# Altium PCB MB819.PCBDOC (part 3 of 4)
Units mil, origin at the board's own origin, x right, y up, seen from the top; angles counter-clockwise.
Board outline 4505 x 6805 mil, 4 copper layers (TopLayer, MidLayer1, GND, BottomLayer), stack 69.6 mil thick; 336 components, 282 nets, 1318 pads, 584 vias.
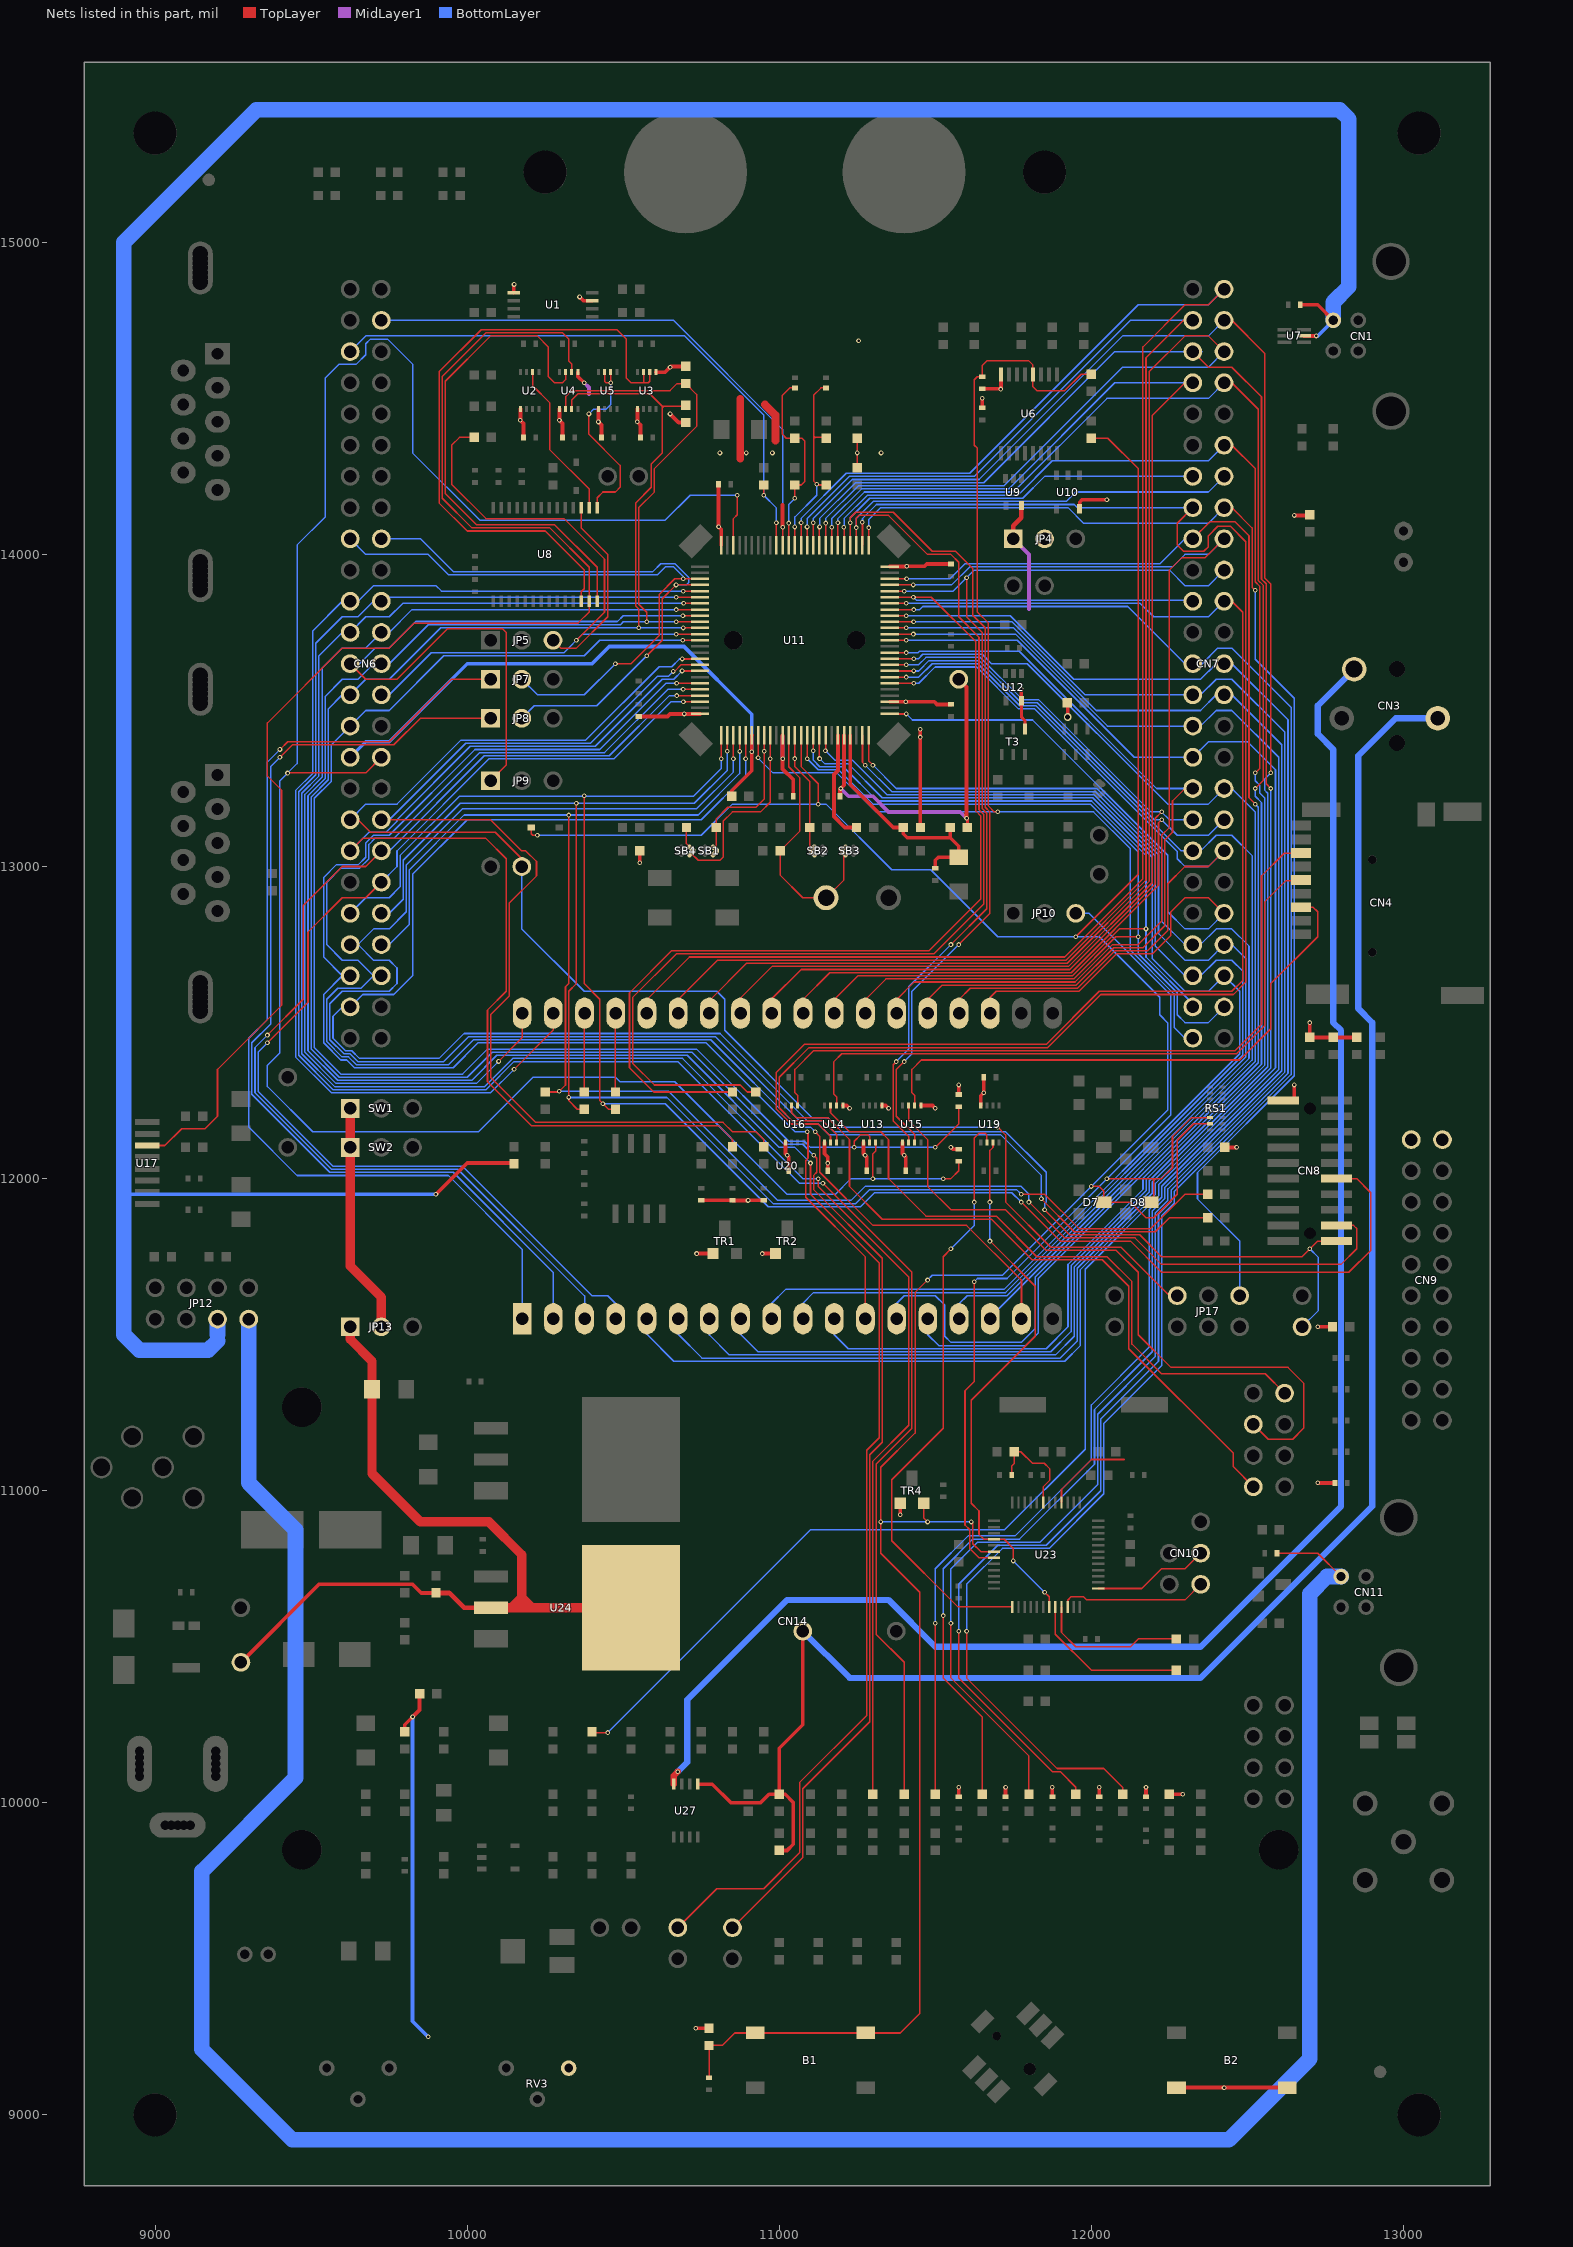
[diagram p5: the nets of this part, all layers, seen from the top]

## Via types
v1: diameter 15, hole 8, TopLayer to BottomLayer, tented both sides, 315 vias
v2: diameter 15, hole 8, TopLayer to BottomLayer, 230 vias
v3: diameter 25, hole 15, TopLayer to BottomLayer, tented both sides, 31 vias
v4: diameter 25, hole 16, TopLayer to BottomLayer, 6 vias
v5: diameter 25, hole 16, TopLayer to BottomLayer, tented both sides, 2 vias

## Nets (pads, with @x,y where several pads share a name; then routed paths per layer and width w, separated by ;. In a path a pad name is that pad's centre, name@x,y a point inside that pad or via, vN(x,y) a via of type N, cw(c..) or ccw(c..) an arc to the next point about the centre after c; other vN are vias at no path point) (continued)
PB5: CN6.35 JP11.1 JP17.2 U11.91 | length 4895.4
  TopLayer w5: CN6.35@9625,13150 9650,13150 9690,13110 10090,13110 10175,13025 JP11.1@10175,13000 ; v2(10689.06,13665) U11.91@10734.06,13665 ; v2(11700,12165) 11725,12140 11725,11925 11870,11780 12095,11780 JP17.2@12250,11625
  BottomLayer w5: CN6.35@9625,13150 9675,13200 9775,13200 9980,13405 10380,13405 10615,13640 10655.15,13640 10680.15,13665 v2(10689.06,13665) ; JP11.1@10175,13000 10175,12800 10375,12600 10800,12600 10825,12575 10825,12475 11105,12195 11155,12195 11185,12165 v2(11700,12165)
PB6: CN6.36 R69.1 U11.92 | length 3511.2
  TopLayer w5: CN6.36@9725,13150 10075,13150 10175,13050 10188,13050 10222,13016 10222,12970 10135,12883 10135,12585 10075,12525 10075,12325 10220,12180 10820,12180 10850,12150 10925,12150 10950,12125 R69.1@10950,12102.5 ; v2(10660,13625) 10664.06,13625 10685.31,13646.26 U11.92@10745.87,13646.26
  BottomLayer w5: CN6.36@9725,13150 9750,13150 9995,13395 10395,13395 10610,13610 10645,13610 v2(10660,13625)
PB7: CN6.37 R62.1 U11.93 | length 3530.1
  TopLayer w5: CN6.37@9625,13050 9665,13090 10060,13090 10125,13025 10125,12600 10065,12540 10065,12310 10205,12170 10805,12170 10850,12125 R62.1@10850,12102.5 ; v2(10688.43,13626.57) U11.93@10745.87,13626.57
  BottomLayer w5: CN6.37@9625,13050 9685,13110 9740,13110 9775,13145 9775,13150 10010,13385 10410,13385 10625,13600 10661.85,13600 v2(10688.43,13626.57)
PB9: CN6.46 U11.96 U20.17 | length 5011.4
  TopLayer w5: v1(10691.48,13567.52) U11.96@10745.87,13567.52 ; v2(11115,12150) 11130,12135 11130,12020 11300,11850 11600,11850 11776,11674 U20.17@11776,11551
  BottomLayer w5: CN6.46@9725,12650 CN6.46@9700,12650 ; v1(10691.48,13567.52) 10642.52,13567.52 10440,13365 10040,13365 9765,13090 9704.14,13090 9685,13070.86 9685,13025 9655,12995 9595,12995 9550,12950 9550,12750 9600,12700 9650,12700 CN6.46@9700,12650 ; v2(11115,12150) 11100,12165 11060,12165 10780,12445 10020,12445 9940,12365 9645,12365 9620,12390 9599.14,12390 9550,12439.14 9550,12575 9585,12610 9660,12610 CN6.46@9700,12650
PB12: CN7.16 JP17.6 U11.51 | length 4095.5
  TopLayer w5: U11.51@11286.22,14029.13 v1(11286.22,14086.22) ; CN7.16@12425,14150 12450,14150 12515,14085 12515,13895 v2(12525,13885)
  BottomLayer w5: v1(11286.22,14086.22) 11286.22,14111.22 11325,14150 11925,14150 11975,14100 12375,14100 CN7.16@12425,14150 ; JP17.6@12475,11625 12475,11800 12340,11935 12340,12019.29 12650,12329.29 12650,13538.89 12525,13663.89 v2(12525,13885)
PB13: CN7.15 U11.52 U14.3 | length 4985.6
  TopLayer w5: U14.3@11183.84,12115.94 11183.84,12141.16 11140,12185 11042.13,12185 11000,12227.13 11000,12325 11095,12420 11860,12420 12030,12590 12455,12590 12495,12630 12495,14040.86 12445.86,14090 12405,14090 12375,14060 12375,14025 12360,14010 12295,14010 12275,14030 12275,14100 CN7.15@12325,14150 ; v1(11266,14103) 11266.54,14102.46 U11.52@11266.54,14029.13
  BottomLayer w5: v1@11266.54,14102.46 11266.54,14115 11311.54,14160 11945,14160 11955,14150 CN7.15@12325,14150
PB14: CN7.14 R58.1 U11.53 | length 4765
  TopLayer w5: R58.1@10925,12277.5 10897.5,12277.5 10875,12300 10600,12300 10530,12370 10530,12580 10670,12720 11495,12720 11655,12880 11655,13166.72 11640,13181.72 11640,13735 11575,13800 11575,13975 11550,14000 11475,14000 11350,14125 11255,14125 11246.85,14116.85 U11.53@11246.85,14029.13
  BottomLayer w5: v1(11246.85,14086.15) 11246.85,14115 11301.85,14170 11920,14170 11950,14200 12375,14200 CN7.14@12425,14250
PB15: CN7.13 U11.54 U15.3 | length 3741.5
  TopLayer w5: U11.54@11227.17,14029.13 11227.17,14117.17 11245,14135 11365,14135 11490,14010 11565,14010 11620,13955 11620,13805 11660,13765 11660,13190 11675,13175 11675,12850 v2(11575,12750) ; v2(11400,12375) 11375,12350 11375,12200 11433.84,12141.16 U15.3@11433.84,12115.94
  BottomLayer w5: v2(11227.17,14101.83) 11227.17,14117.17 11290,14180 11780,14180 11850,14250 CN7.13@12325,14250 ; v2(11400,12375) 11425,12400 11425,12600 v2(11575,12750)
PC6: R14.1 R23.1 R30.1 U11.63 | length 646.4
  TopLayer w5: U11.63@11050,14029.13 v1(11050,14088) ; 11110,14370 11115,14375 11110,14380 ; 11110,14375 R23.1@11147.5,14375 ; R30.1@11150,14222.5 11122.5,14222.5 11110,14235 11110,14510 11133.5,14533.5 R14.1@11150,14533.5
  BottomLayer w5: v1(11050,14088) 11050,14120 11120,14190 v1(11120,14225)
PC7: R13.1 R22.1 R28.2 U11.64 | length 622.1
  TopLayer w5: U11.64@11030.31,14029.13 v1(11030.31,14100.69) ; v1(11050,14180) R28.2@11050,14222.5 11070.5,14222.5 11081,14233 11081,14364 11072.5,14372.5 11022.5,14372.5 11010,14385 11010,14510 11033.5,14533.5 R13.1@11050,14533.5
  BottomLayer w5: v1@11030,14101 11030,14160 v1(11050,14180)
PC8: C18.1 CN6.4 R24.1 U11.65 | length 2289.3
  TopLayer w5: 11009.97,14159.1 11010.63,14158.44 ; U11.65@11010.63,14029.13 v1(11010.63,14087.37) ; C18.1@11250,14277.5 R24.1@11250,14372.5
  TopLayer w12: v1(11010.63,14087.37) 11010.63,14158.44
  TopLayer w25: 10875,14307 10875,14499 ; 10954,14480 10987.5,14446.5 10987.5,14365.16
  BottomLayer w5: CN6.4@9725,14750 10660.86,14750 11010.63,14400.23 v1(11010.63,14087.37)
  other v1: 10810,14325 10894,14325 10978,14325 11250,14325 11326,14325 11254,14685
PC9: CN6.5 R29.1 U11.66 | length 1917.7
  TopLayer w5: v1(10950,14190) R29.1@10950,14222.5 ; U11.66@10990.94,14029.13 v1(10990.94,14101.94)
  BottomLayer w5: CN6.5@9625,14650 9675,14700 10696.72,14700 10950,14446.72 v1(10950,14190) 10990.94,14149.06 v1(10990.94,14101.94)
PC10: CN6.17 JP7.2 U11.78 | length 1968.3
  TopLayer w5: v2(10475,13650) 10525,13650 10615,13740 10615,13871.85 10665,13921.85 U11.78@10745.87,13921.85
  BottomLayer w5: CN6.17@9625,14050 9675,14000 9875,14000 9940,13935 10610,13935 10635,13960 10661.86,13960 10691.85,13930.01 v1(10691.85,13921.85) ; JP7.2@10175,13600 10225,13550 10375,13550 v2(10475,13650)
PC11: CN6.18 JP8.2 U11.79 | length 1942.9
  TopLayer w5: v2(10575,13675) 10625,13725 10625,13858 v1(10669.17,13902.17) U11.79@10745.87,13902.17
  BottomLayer w5: CN6.18@9725,14050 9850,14050 9955,13945 10595,13945 10620,13970 10666,13970 10710,13926 10710,13910 10702.17,13902.17 v1(10669.17,13902.17) ; JP8.2@10175,13475 10215,13515 10415,13515 v2(10575,13675)
PC13: CN7.49 R26.2 R31.1 U6.12 U11.7 | length 4036.1
  TopLayer w5: v2(10931.89,13348.11) U11.7@10931.89,13420.87 ; v2(11700,13175) 11689.14,13175 11670,13194.14 11670,13780 11635,13815 11635,14340 11625,14350 11625,14560 11634.5,14569.5 R26.2@11650,14569.5 11650,14605 11665,14620 11800,14620 11812.8,14607.2 11812.8,14537.2 11825,14525 11915,14525 11967.5,14577.5 R31.1@12000,14577.5
  BottomLayer w5: v2(10931.89,13348.11) 10980,13300 11185,13300 11310,13175 12007.01,13175 12125,13057.01 12125,12731.72 12265,12591.72 12265,12485 12300,12450 CN7.49@12325,12450
PC14: R37.2 SB1.1 U11.8 | length 489
  TopLayer w5: SB1.1@10800,13050 10797.5,13052.5 10797.5,13152.5 10835,13190 10925,13190 10951.57,13216.57 U11.8@10951.57,13420.87 ; v1@10951.57,13369.43 v1(10952,13369)
PC15: R38.2 SB4.1 U11.9 | length 694.9
  TopLayer w5: R38.2@10702.5,13125 10702.5,13073.5 SB4.1@10718,13058 ; SB4.1@10718,13042 10740,13020 10810,13020 10820,13030 10820,13145 10850,13175 10940,13175 10971.26,13206.26 U11.9@10971.26,13420.87
  other v1: 10971.26,13345.74
PD0: CN6.22 R111.1 U11.81 | length 6714.7
  TopLayer w5: v1(10669.8,13862.8) U11.81@10745.87,13862.8 ; v2(11140,11985) 11425,11700 11425,11200 11310,11085 11310,10540 11400,10450 R111.1@11400,10027.5
  MidLayer1 w5: CN6.22@9705,13850 CN6.22@9725,13850
  BottomLayer w5: CN6.22@9700,13850 9650,13800 9600,13800 9515,13715 9515,13294.29 9460,13239.29 9460,12395 9570,12285 10060,12285 10150,12375 10675,12375 11065,11985 v2(11140,11985) ; CN6.22@9725,13850 9737.8,13862.8 v1(10669.8,13862.8)
PD1: CN6.23 R125.1 U11.82 | length 6648.8
  TopLayer w5: v1(10693.11,13843.11) U11.82@10745.87,13843.11 ; v2(11125,12000) 11125,11975 11415,11685 11415,11210 11300,11095 R125.1@11300,10027.5
  MidLayer1 w5: CN6.23@9600,13750 CN6.23@9625,13750
  BottomLayer w5: v1(10693.11,13843.11) 9793.11,13843.11 9750,13800 9675,13800 CN6.23@9625,13750 9600,13750 9525,13675 9525,13290.15 9470,13235.15 9470,12400 9575,12295 10055.86,12295 10145.86,12385 10690,12385 11075,12000 v2(11125,12000)
PD3: CN6.25 JP9.1 U11.84 | length 2273.5
  TopLayer w5: CN6.25@9625,13650 9675,13600 9775,13600 9937.5,13762.5 10112.5,13762.5 10125,13750 10125,13325 JP9.1@10075,13275 ; v1(10691.26,13803.74) U11.84@10745.87,13803.74
  BottomLayer w5: CN6.25@9625,13650 9655,13650 9705,13700 9750,13700 9835,13785 10481.26,13785 10500,13803.74 v1(10691.26,13803.74)
PD4: CN6.26 JP18.2 R12.1 U4.2 U11.85 | length 8485.7
  TopLayer w5: U4.2@10315.16,14465.94 10315.16,14505.16 10335,14525 10650,14525 10672.5,14547.5 R12.1@10700,14547.5 10735,14512.5 10735,14410 10600,14275 10600,14200 10550,14150 10550,13840 10575,13815 v2(10575,13784.06) ; v1(10669.94,13784.06) U11.85@10745.87,13784.06 ; JP18.2@10675,9600 10800,9725 10950,9725 11065,9840 11065,10065 11280,10280 11280,11130 11320,11170 11320,11730 11100,11950 v2(11100,12050)
  BottomLayer w5: v1(10669.94,13784.06) 10500,13784.06 10490.94,13775 9875,13775 9750,13650 9700,13650 9650,13600 9600,13600 9545,13545 9545,13281.86 9490,13226.86 9490,12410 9585,12315 10015,12315 10095,12395 10705,12395 11000,12100 11050,12100 v2(11100,12050)
PD5: CN6.27 JP19.2 R21.1 U4.3 U11.86 | length 8173.9
  TopLayer w5: U4.3@10334.84,14465.94 10334.84,14494.84 10355,14515 10585,14515 10625,14475 ; v2(10550,13765) 10550,13825 10540,13835 10540,14165 10590,14215 10590,14290 10625,14325 10625,14475 ; 10625,14470 10630,14475 ; v1(10692.63,13764.37) U11.86@10745.87,13764.37 ; R21.1@10697.5,14475 10625,14475 ; JP19.2@10850,9600 11075,9825 11075,10045 11290,10260 11290,11115 11330,11155 11330,11745 11110,11965 11110,12010 11120,12020 11120,12065 v2(11110,12075)
  BottomLayer w5: v1@10692,13765 9915,13765 9750,13600 9675,13600 CN6.27@9625,13550 9600,13550 9555,13505 9555,13277.72 9500,13222.72 9500,12415 9590,12325 10000,12325 10080,12405 10720,12405 11015,12110 11075,12110 v2(11110,12075)
PD6: CN6.28 R19.1 U11.87 | length 2196.1
  TopLayer w5: R19.1@10022.5,14375 9975,14375 9950,14350 9950,14225 10060,14115 10310,14115 10440,13985 10440,13815 v2(10350,13725) ; v1(10670.31,13744.69) U11.87@10745.87,13744.69
  BottomLayer w5: CN6.28@9725,13550 9750,13550 9885,13685 10310,13685 10369.69,13744.69 v1(10670.31,13744.69)
PD7: CN6.29 R59.2 U11.88 U13.2 | length 4761.9
  TopLayer w5: v1(10691,13725) U11.88@10745.87,13725 ; v2(11240,12100) 11240,12120 11260,12140 11285,12140 11289.16,12135.84 U13.2@11289.16,12115.94 ; v2(11500,12100) 11575,12175 R59.2@11575,12230.5
  BottomLayer w5: v1(10691,13725) 10425,13725 10375,13675 9925,13675 9750,13500 9675,13500 9565,13390 9565,13273.58 9510,13218.58 9510,12420 9595,12335 9985,12335 10065,12415 10735,12415 11030,12120 11080,12120 11100,12100 v2(11500,12100)
PE2: CN6.41 CN8.12 R77.1 U11.1 | length 5680.1
  TopLayer w5: v2(10375,13227) 10375,12625 10425,12575 10425,12250 10452.5,12222.5 R77.1@10475,12222.5 ; v1(10813.78,13345.22) U11.1@10813.78,13420.87 ; v2(11775,11925) 11900,11800 12125,11800 12225,11700 12825,11700 12895,11770 12895,11955 12850,12000 CN8.12@12775,12000
  BottomLayer w5: CN6.41@9625,12850 9675,12900 9750,12900 9785,12935 9785,13035 9975,13225 10373,13225 v2(10375,13227) ; v2@10375,13225 10725,13225 10813.78,13313.78 v1(10813.78,13345.22) ; v2(10435,12240) 10635,12240 10965,11910 11260,11910 11305,11955 11745,11955 v2(11775,11925)
PE3: CN6.42 R70.2 R78.1 U11.2 | length 4812.6
  TopLayer w5: v2(10350,13203) 10350,12625 10325,12600 10325,12250 10352.5,12222.5 R78.1@10375,12222.5 ; v1@10833.46,13369.46 U11.2@10833.46,13420.87 ; v2(11775,11950) 11850,11950 11960,11840 12190,11840 12300,11950 R70.2@12372.5,11950
  BottomLayer w5: CN6.42@9725,12850 9750,12850 9795,12895 9795,13020 9977.5,13202.5 v2@10350,13202.5 ; v2(10325,12260) 10640,12260 10980,11920 11245,11920 11290,11965 11760,11965 v2(11775,11950) ; v2(10350,13203) 10350.5,13202.5 10727.5,13202.5 10833,13308 v1(10833,13369)
PE4: CN6.43 R71.2 U11.3 | length 5421.7
  TopLayer w5: v1@10853.15,13345.15 U11.3@10853.15,13420.87 ; v2(11840,11935) 11945,11830 12205,11830 12250,11875 R71.2@12372.5,11875
  BottomLayer w5: CN6.43@9625,12750 CN6.43@9650,12750 ; v1(10853,13345) 10853,13303 10735,13185 9985,13185 9805,13005 9805,12855 9750,12800 9700,12800 CN6.43@9650,12750 ; v2(11840,11935) 11840,12010 11710,12140 11160,12140 11125,12175 11075,12175 10795,12455 10005,12455 9925,12375 9649.14,12375 9624.14,12400 9605,12400 9560,12445 9560,12560 9600,12600 9750,12600 9775,12625 9775,12675 9750,12700 9700,12700 CN6.43@9650,12750
PE5: CN6.44 CN8.18 R88.1 U11.4 | length 5535.4
  TopLayer w5: R88.1@10250,12277.5 10292.5,12277.5 10315,12300 10315,12615 10325,12625 v2(10325,13165) ; v1(10872.83,13368.83) U11.4@10872.83,13420.87 ; v2(11800,11925) 11915,11810 12140,11810 12225,11725 12800,11725 12850,11775 12850,11840 12840,11850 CN8.18@12785,11850
  BottomLayer w5: CN6.44@9725,12750 9750,12750 9815,12815 9815,12990 9990,13165 10740,13165 10872.83,13297.83 v1(10872.83,13368.83) ; v2(10295,12280) 10645,12280 10995,11930 11230,11930 11275,11975 11775,11975 11800,11950 v2(11800,11925)
PE6: CN6.47 CN8.20 JP2.2 U11.5 | length 5982.9
  TopLayer w5: v1@10892.52,13345.52 U11.5@10892.52,13420.87 ; v2(11850,11900) 11930,11820 12155,11820 12225,11750 12675,11750 12725,11800 CN8.20@12785,11800
  BottomLayer w5: v1(10892,13345) 10892,13292 10750,13150 10000,13150 9825,12975 9825,12650 9765,12590 9665,12590 CN6.47@9625,12550 9600,12550 9570,12520 9570,12450 9610,12410 9630,12410 9655,12385 9910,12385 9990,12465 10810,12465 11090,12185 11140,12185 11175,12150 11725,12150 11855,12020 11855,11925 11850,11920 v2(11850,11900) ; JP2.2@12675,11525 12727.5,11577.5 12727.5,11747.5 v2(12700,11775)
PE7: CN7.31 R75.1 U11.38 | length 5837.5
  TopLayer w5: R75.1@10402.5,10225 v2(10450,10225) ; U11.38@11354.13,13725 v1(11407,13725) ; CN7.31@12325,13350 CN7.31@12330,13350
  BottomLayer w5: v2(10450,10225) 11100,10875 11722,10875 11980,11133 11980,11709.29 12215.33,11944.62 12215.33,11980.48 12590,12355.15 12590,13310 12500,13400 12375,13400 CN7.31@12325,13350 12137.26,13350 11762.26,13725 v1(11407,13725)
PE8: CN7.29 R112.2 U11.39 | length 5316.8
  TopLayer w5: U11.39@11354.13,13744.69 v1@11429.69,13744.69 ; R112.2@11500,10027.5 v2(11500,10575)
  BottomLayer w5: v1@11429.69,13744.69 11756.72,13744.69 12051.4,13450 12350,13450 12400,13500 12450,13500 12600,13350 12600,12350 12225.33,11975.33 12225.33,11940.48 12185,11900.15 12185,11460 12000,11275 12000,11100 11755,10855 11605,10855 11500,10750 v2(11500,10575)
  other v1: 11430,13745
PE9: CN7.28 R126.2 U11.40 | length 5378.9
  TopLayer w5: U11.40@11354.13,13764.37 v1@11406.37,13764.37 ; v2(11525,10600) 11525,10400 11650,10275 R126.2@11650,10027.5
  BottomLayer w5: v1@11406.37,13764.37 11751.18,13764.37 12015.55,13500 12350,13500 CN7.28@12400,13550 ; v2(11525,10600) 11525,10750 11620,10845 11770.01,10845 12010,11084.99 12010,11260 12195,11445 12195,11896 12235.33,11936.34 12235.33,11971.19 12610,12345.86 12610,13390 12450,13550 CN7.28@12425,13550
  other v1: 11407,13765
PE10: CN7.27 R127.2 U11.41 | length 5520.4
  TopLayer w5: U11.41@11354.13,13784.06 v1(11430.06,13784.06) ; v2(11550,10575) 11550,10400 11800,10150 R127.2@11800,10027.5
  BottomLayer w5: v1(11430.06,13784.06) 11745.63,13784.06 11979.69,13550 12350,13550 12400,13600 12450,13600 12620,13430 12620,12341.72 12245.33,11967.05 12245.33,11930.33 12205,11890 12205,11430 12020,11245 12020,11020 11835,10835 11635,10835 11550,10750 v2(11550,10575)
PE11: CN7.26 R117.2 U11.42 | length 5570.8
  TopLayer w5: U11.42@11354.13,13803.74 v1(11407.26,13803.74) ; v2(11575,10550) 11575,10400 11875,10100 11900,10100 11950,10050 R117.2@11950,10027.5
  BottomLayer w5: v1(11407.26,13803.74) 11740.09,13803.74 11943.83,13600 12350,13600 CN7.26@12400,13650 ; v2(11575,10550) 11575,10700 11700,10825 11855,10825 12030,11000 12030,11230 12215,11415 12215,11885 12255.33,11925.33 12255.33,11962.91 12630,12337.57 12630,13470 12450,13650 CN7.26@12425,13650
PE12: CN7.25 R118.2 U11.43 | length 5761.3
  TopLayer w5: U11.43@11354.13,13823.43 v1(11430.57,13823.43) ; v2(11600,10550) 11600,10400 11890,10110 12040,10110 12100,10050 R118.2@12100,10027.5
  BottomLayer w5: v1(11430.57,13823.43) 11450,13823.43 11459.69,13833.11 12116.89,13833.11 12300,13650 12355,13650 12405,13700 12450,13700 12640,13510 12640,12333.43 12265.33,11958.77 12265.33,11921.19 12225,11880.86 12225,11400 12040,11215 12040,10990 11865,10815 11715,10815 11600,10700 v2(11600,10550)
PE13: CN7.22 U11.44 U14.2 | length 4328.3
  TopLayer w5: U14.2@11164.16,12115.94 11164.16,12135.84 11125,12175 11037.98,12175 10990,12222.98 10990,12340 11080,12430 11855,12430 12025,12600 12450,12600 12485,12635 12485,13815 12450,13850 CN7.22@12425,13850 ; U11.44@11354.13,13843.11 v1(11407.11,13843.11)
  BottomLayer w5: v1(11407.11,13843.11) 12156.89,13843.11 12200,13800 12375,13800 CN7.22@12425,13850
PE14: CN7.21 R57.1 U11.45 | length 3913.5
  TopLayer w5: R57.1@10850,12277.5 10597.5,12277.5 10520,12355 10520,12595 10655,12730 11480,12730 11645,12895 11645,13162.57 11630,13177.57 11630,13720 11487,13863 v1(11430,13863) ; U11.45@11354.13,13862.8 v1@11429.8,13862.8
  BottomLayer w5: v1(11430,13863) 11439.89,13853.11 CN7.21@12321.89,13853.11
PE15: CN7.20 U11.46 U15.2 | length 3120.9
  TopLayer w5: U11.46@11354.13,13882.48 v2(11400,13882.48) ; v2(11375,12375) 11365,12365 11365,12185 11414.16,12135.84 U15.2@11414.16,12115.94 ; v2(11550,12750) 11665,12865 11665,13170.86 11650,13185.86 11650,13750 11600,13800 v2(11600,13925)
  BottomLayer w5: v2(11375,12375) 11415,12415 11415,12615 v2(11550,12750) ; v2(11400,13882.48) 11557.48,13882.48 11625,13950 12250,13950 12300,13900 12375,13900 CN7.20@12425,13950
PH0: C30.1 SB3.1 U11.12 X2.2 | length 834.1
  TopLayer w5: 11030,13370 11030,13320 11065,13285 11065,13112.5 C30.1@11002.5,13050 11002.5,12972.5 11075,12900 X2.2@11150,12900 ; 11030.31,13370.31 U11.12@11030.31,13420.87 ; X2.2@11150,12902.5 X2.2@11150,12900 ; SB3.1@11207,13042 11207,12957 X2.2@11150,12900
PH1: R39.1 SB2.1 U11.13 | length 386.5
  TopLayer w5: U11.13@11050,13420.87 11050,13320 11097.5,13272.5 11097.5,13067.5 SB2.1@11107,13058
  other v1: 11050,13346
PH2: CN6.32 R64.2 U11.73 U13.3 | length 7350.6
  TopLayer w5: v2(9424.4,13299.4) 9425,13300 9675,13300 CN6.32@9725,13350 ; U11.73@10853.15,14029.13 10853.15,14115 10865,14126.85 v2(10865,14190) ; v2(11300,12000) 11300,12080 11308.84,12088.84 U13.3@11308.84,12115.94 ; v2(11525,12000) 11550,12000 11575,12025 R64.2@11575,12055.5
  BottomLayer w5: v2(10865,14190) 10715,14190 10635,14110 10040,14110 9825,14325 9825,14610 9745,14690 9690,14690 9675,14675 9675,14640 9645,14610 9590,14610 9545,14565 9545,14120 9455,14030 9455,13330 9400,13275 9400,12403.28 9360,12363.28 9360,12295 9505,12150 10035.86,12150 10210.86,12325 10475,12325 10490,12310 10665,12310 11025,11950 11180,11950 11230,12000 v2(11525,12000)
RESET#: B1.2 B1.3 C85.2 D2.1 D7.3 R49.2 R137.1 RS1.13 TR4.1 U11.14 U23.18 | length 10176.3
  TopLayer w5: D2.1@10205,13125 10205,13105 10210,13100 v2(10225,13100) ; C85.2@10775,9119.5 R137.1@10775,9222.5 10817.5,9222.5 10857.5,9262.5 11387.5,9262.5 11450,9325 11450,10675 11325,10800 11325,11075 11435,11185 11435,11635 v2(11475,11675) ; U11.14@11069.68,13420.87 11069.68,13320.32 11125,13265 v2(11125,13200) ; TR4.1@11462.5,10960 11462.5,10912.5 v2(11475,10900) ; v2(11615,10900) 11620,10895 11620,10830 11645.16,10804.84 U23.18@11687.68,10804.84 ; v2(11950,12775) 12150,12975 12150,14275 12052.5,14372.5 R49.2@12000,14372.5 ; v2(12000,11975) 12025,11975 12040,11960 D7.3@12040,11924.5 12125.5,11924.5 12175,11875 12200,11875 12275,11950 12275,12123 12327.79,12175.79 RS1.13@12380,12175.79
  BottomLayer w5: v2(10225,13100) 10750,13100 10850,13200 11150,13200 11360,12990 11485,12990 11700,12775 12025,12775 12218.99,12581.01 12218.99,12525 12245,12498.99 12245,12220 11715,11690 11490,11690 v2(11475,11675) ; v2(11325,10900) v2(11615,10900)
SEG0: CN7.44 U11.24 U20.15 | length 3375.3
  TopLayer w5: U11.24@11266.54,13420.87 11266.54,13333.46 v2(11275,13325)
  BottomLayer w5: v2(11275,13325) 11360,13240 12012.72,13240 12215,13037.72 12215,12785 12300,12700 12375,12700 CN7.44@12425,12750 12450,12750 12495,12705 12495,12390 11730,11625 11602,11625 11576,11599 U20.15@11576,11551
SEG1: CN7.43 U11.25 U20.16 | length 3252.7
  TopLayer w5: U11.25@11286.22,13420.87 11286.22,13338.78 v2(11300,13325)
  BottomLayer w5: v2(11300,13325) 11375,13250 12016.86,13250 12225,13041.86 12225,12825 12300,12750 12350,12750 12400,12800 12450,12800 12505,12745 12505,12385 11676,11556 U20.16@11676,11551
SEG2: CN7.42 U11.26 U20.21 | length 2504.7
  TopLayer w5: U11.26@11354.13,13488.78 v1(11407.22,13488.78) ; U20.21@11676,12530 11676,12581 11695,12600 11960,12600 12080,12720 12195,12720 12255,12780 12255,12855 12300,12900 12375,12900 CN7.42@12425,12850
  BottomLayer w5: v1(11407.22,13488.78) 11426.57,13469.43 11811.57,13469.43 12245,13036 12245,12855 12300,12800 12375,12800 CN7.42@12425,12850 CN7.42@12450,12850
SEG3: CN7.38 U11.31 U20.22 | length 2571.1
  TopLayer w5: U11.31@11354.13,13587.2 v1(11430.8,13587.2) ; U20.22@11575,12531 U20.22@11576,12530 11576,12574 11612,12610 11955.86,12610 12075.86,12730 12180,12730 12245,12795 12245,12945 12300,13000 12375,13000 CN7.38@12425,13050
  BottomLayer w5: v1(11430.8,13587.2) 11447.2,13587.2 11499.3,13639.3 11632.42,13639.3 11766.72,13505 11818.43,13505 12275,13048.43 12275,13025 12300,13000 12375,13000 CN7.38@12425,13050
SEG4: CN7.37 U11.32 U20.13 | length 3896.1
  TopLayer w5: U11.32@11354.13,13606.89 11406.89,13606.89 v1(11407,13607)
  BottomLayer w5: U20.13@11376,11551 11376,11601 11400,11625 11500,11625 11530,11595 11530,11495 11550,11475 11775,11475 11820,11520 11820,11685 12515,12380 12515,13035 12450,13100 12400,13100 CN7.37@12350,13050 ; v1@11406.89,13606.89 11446.89,13606.89 11489.9,13649.9 11635.96,13649.9 11770.86,13515 11822.57,13515 12287.57,13050 CN7.37@12325,13050
SEG5: CN7.34 U11.35 U20.14 | length 3821.2
  TopLayer w5: U11.35@11354.13,13665.94 v1(11430.94,13665.94)
  BottomLayer w5: v1(11430.94,13665.94) 11445.94,13665.94 11460,13680 11650,13680 11680,13650 11794.83,13650 12244.83,13200 12375,13200 CN7.34@12425,13250 12450,13250 12525,13175 12525,12375 11830,11680 11830,11505 11790,11465 11511,11465 11476,11500 U20.14@11476,11551
SEG6: CN7.33 U11.36 U20.23 | length 2547.6
  TopLayer w5: U11.36@11354.13,13685.63 v1(11406.63,13685.63) ; U20.23@11476,12530 11476,12574 11522,12620 11951.72,12620 12071.72,12740 12165,12740 12235,12810 12235,13085 12260,13110 12260,13210 12300,13250 CN7.33@12325,13250
  BottomLayer w5: v1(11406.63,13685.63) 11445.63,13685.63 11450,13690 11768.98,13690 12208.98,13250 CN7.33@12325,13250
SEG10: CN7.18 U11.47 U20.24 | length 3480.8
  TopLayer w5: U11.47@11354.13,13902.17 v1(11429.17,13902.17) ; U20.24@11376,12530 11376,12574 11432,12630 11947.57,12630 12067.57,12750 12150,12750 12225,12825 12225,13100 12250,13125 12250,13950 12290,13990 12365,13990 CN7.18@12425,14050
  BottomLayer w5: v1(11429.17,13902.17) 11552.17,13902.17 11610,13960 12260,13960 12300,14000 12375,14000 CN7.18@12425,14050
SEG11: CN7.17 U11.48 U20.11 | length 4893.1
  TopLayer w5: U11.48@11354.13,13921.85 v1(11407.85,13921.85) ; CN7.17@12325,14050 12380,14105 12460,14105 12505,14060 12505,13220 v2(12525,13200)
  BottomLayer w5: U20.11@11176,11551 11176,11500 11221,11455 11855,11455 11925,11525 11925,11725 12165.33,11965.33 12165.33,12001.19 12535,12370.86 12535,13190 v2(12525,13200) ; v1(11407.85,13921.85) 11546.85,13921.85 11595,13970 12220,13970 12300,14050 CN7.17@12325,14050
SEG16: CN6.45 U11.95 U20.12 | length 4486.3
  TopLayer w5: v1(10670.8,13587.2) U11.95@10745.87,13587.2 ; v2(11090,12150) 11092.03,12147.97 11092.03,12065 11084.5,12057.47 11084.5,11940.5 11276,11749 U20.12@11276,11551
  BottomLayer w5: v1(10670.8,13587.2) 10637.2,13587.2 10425,13375 10025,13375 9750,13100 9700,13100 9675,13075 9675,13030 9650,13005 9580,13005 9540,12965 9540,12710 9600,12650 9540,12590 9540,12435 9595,12380 9614.14,12380 9639.14,12355 9955,12355 10035,12435 10765,12435 11050,12150 v2(11090,12150)
SEG18: CN7.48 U11.15 U20.25 | length 3015.2
  TopLayer w5: v1(11089.37,13345.63) U11.15@11089.37,13420.87 ; U20.25@11276,12530 11276,12574 11342,12640 11943.43,12640 12078.43,12775 v2(12150,12775)
  BottomLayer w5: v1(11089.37,13345.63) 11125,13310 11190,13310 11300,13200 11996.15,13200 12150,13046.15 12150,12720.86 12275,12595.86 12275,12525 12300,12500 12375,12500 CN7.48@12425,12550
SEG19: CN7.47 U11.16 U20.26 | length 2956.5
  TopLayer w5: v1@11109.06,13371.06 U11.16@11109.06,13420.87 ; U20.26@11176,12530 11176,12574 11252,12650 11939.29,12650 12089.29,12800 v2(12175,12800)
  BottomLayer w5: v1(11109,13371) 11109,13341 11130,13320 11205,13320 11315,13210 12000.29,13210 12175,13035.29 12175,12710 12325,12560 CN7.47@12325,12550
SEG20: CN7.46 U11.17 U20.9 | length 4041.4
  TopLayer w5: U11.17@11128.74,13420.87 11128.74,13346.26 v1(11129,13346)
  BottomLayer w5: U20.9@10976,11551 10976,11601 11020,11645 11720,11645 12475,12400 12475,12600 CN7.46@12425,12650 12375,12600 12300,12600 12195,12705 12195,13029.44 12004.44,13220 11330,13220 11220,13330 11145,13330 v1(11129,13346)
SEG21: CN7.45 U11.18 U20.10 | length 3947.2
  TopLayer w5: v1@11148.43,13371.43 U11.18@11148.43,13420.87
  BottomLayer w5: U20.10@11076,11551 11076,11601 11110,11635 11725,11635 12485,12395 12485,12665 12450,12700 12400,12700 12350,12650 12300,12650 12205,12745 12205,13033.58 12008.58,13230 11345,13230 11235,13340 11179,13340 v1(11148,13371)
SEG22: CN7.36 U11.33 U20.27 | length 2886.2
  TopLayer w5: U20.27@11076,12530 11076,12574 11162,12660 11935.15,12660 12215,12939.85 12215,13140 v2(12225,13150) ; U11.33@11354.13,13626.57 v1(11430.57,13626.57)
  BottomLayer w5: v1(11430.57,13626.57) 11446.57,13626.57 11480,13660 11640,13660 11775,13525 11826.72,13525 12201.72,13150 v2(12225,13150) 12275,13100 12375,13100 CN7.36@12425,13150
SEG23: CN7.35 U11.34 U20.28 | length 2933.8
  TopLayer w5: U20.28@10976,12530 10976,12576 11070,12670 11931,12670 12205,12944 12205,13155 v2(12225,13175) ; U11.34@11354.13,13646.26 v1(11407.26,13646.26) ; CN7.35@12300,13150 CN7.35@12325,13150
  MidLayer1 w5: U20.28@10976,12530 U20.28@10976,12576
  BottomLayer w5: v1(11407.26,13646.26) 11446.26,13646.26 11470,13670 11644.14,13670 11779.14,13535 11830.86,13535 12190.86,13175 v2(12225,13175) 12250,13150 CN7.35@12325,13150
SEG28: CN7.12 U11.55 U20.7 | length 5861.7
  TopLayer w5: U11.55@11207.48,14029.13 v1@11207.48,14086.52 ; CN7.12@12425,14350 12450,14350 12525,14275 12525,13912.57 12540,13897.57 12540,13315 v2(12525,13300)
  BottomLayer w5: U20.7@10776,11551 10776,11499 10840,11435 11885,11435 11945,11495 11945,11716.72 12185.33,11957.05 12185.33,11992.91 12555,12362.57 12555,13220 12540,13235 12540,13260 12525,13275 v2(12525,13300) ; v1@11207.48,14086.52 11207.48,14115 11282.48,14190 11765,14190 11875,14300 12375,14300 CN7.12@12425,14350
  other v1: 11207,14087
SEG29: CN7.8 U11.56 U20.8 | length 6040
  TopLayer w5: U11.56@11187.8,14029.13 11187.8,14101.8 v1(11188,14102) ; CN7.8@12425,14550 12450,14550 12535,14465 12535,13916.72 12550,13901.72 12550,13275 v2(12525,13250)
  BottomLayer w5: U20.8@10876,11551 10876,11501 10932,11445 11870,11445 11935,11510 11935,11720.86 12175.33,11961.19 12175.33,11997.05 12545,12366.72 12545,13205 12525,13225 v2(12525,13250) ; v1(11188,14102) 11188,14115 11273,14200 11750,14200 12050,14500 12375,14500 CN7.8@12425,14550
SEG30: CN7.7 U11.57 U20.29 | length 4684.2
  TopLayer w5: U20.29@10876,12530 10876,12579 10977,12680 11926.86,12680 12195,12948.14 12195,14445 12300,14550 CN7.7@12325,14550 ; U11.57@11168.11,14029.13 v1@11168.11,14086.89
  MidLayer1 w5: U20.29@10876,12530 U20.29@10876,12575 ; CN7.7@12300,14550 CN7.7@12325,14550
  BottomLayer w5: v1@11168.11,14086.89 11168.11,14115 11263.11,14210 11735,14210 12075,14550 CN7.7@12325,14550
  other v1: 11168,14087
SEG31: CN7.6 U11.58 U20.30 | length 5178
  TopLayer w5: U20.30@10776,12530 10776,12571 10895,12690 11922.72,12690 12185,12952.28 12185,14585 12300,14700 12375,14700 CN7.6@12425,14650 ; U11.58@11148.43,14029.13 v1(11148.43,14100.57)
  MidLayer1 w5: U20.30@10776,12530 U20.30@10776,12575
  BottomLayer w5: v1(11148.43,14100.57) 11148.43,14115 11253.43,14220 11720,14220 12100,14600 12375,14600 CN7.6@12425,14650
SEG32: CN7.5 U11.59 U20.5 | length 6613.7
  TopLayer w5: U11.59@11128.74,14029.13 v1@11128.74,14087.74 ; CN7.5@12325,14650 12375,14600 12450,14600 12545,14505 12545,13920.86 12560,13905.86 12560,13265 v2(12575,13250)
  BottomLayer w5: U20.5@10576,11551 10576,11501 10662,11415 11915,11415 11965,11465 11965,11708.43 12205.33,11948.77 12205.33,11984.62 12575,12354.29 v2(12575,13250) ; v1(11129,14088) 11129,14115 11244,14230 11655,14230 12075,14650 12355,14650
SEG33: CN7.4 U11.60 U20.6 | length 6660
  TopLayer w5: U11.60@11109.06,14029.13 v1@11109.06,14100.94 ; CN7.4@12425,14750 12450,14750 12555,14645 12555,13925 12575,13905 v2(12575,13300)
  BottomLayer w5: U20.6@10676,11551 10676,11501 10752,11425 11900,11425 11955,11480 11955,11712.57 12195.33,11952.91 12195.33,11988.77 12565,12358.43 12565,13235 12555,13245 12555,13280 v2(12575,13300) ; v1@11109.06,14100.94 11109.06,14115 11184.92,14190.87 11234.06,14240 11640,14240 12100,14700 12375,14700 CN7.4@12425,14750
  other v1: 11109,14101
SEG34: CN7.3 U11.61 U20.31 | length 5184.7
  TopLayer w5: U20.31@10676,12530 10676,12574 10802,12700 11918.58,12700 12175,12956.42 12175,14630 12295,14750 CN7.3@12325,14750 ; v1(11089,14088) 11089.37,14087.63 U11.61@11089.37,14029.13
  MidLayer1 w5: CN7.3@12300,14750 CN7.3@12325,14750
  BottomLayer w5: v1@11089.37,14087.63 11089.37,14115 11224.37,14250 11625,14250 12125,14750 CN7.3@12325,14750
SEG35: CN7.2 U11.62 U20.32 | length 5579.8
  TopLayer w5: U20.32@10576,12530 10576,12574 10712,12710 11914.44,12710 12165,12960.56 12165,14665 12300,14800 12375,14800 CN7.2@12425,14850 ; U11.62@11069.68,14029.13 v1(11069.68,14101.32)
  BottomLayer w5: v1(11069.68,14101.32) 11069.68,14115 11214.68,14260 11610,14260 12150,14800 12375,14800 CN7.2@12425,14850
SEG36: CN6.38 U11.97 U20.3 | length 3637.4
  TopLayer w5: v2(9360,12460) 9475,12575 9475,12875 9600,13000 9675,13000 CN6.38@9725,13050 CN6.38@9700,13050 ; v1(10671.83,13547.83) U11.97@10745.87,13547.83
  BottomLayer w5: v2(9360,12460) 9320,12420 9320,12275 9565,12030 9970,12030 10376,11624 U20.3@10376,11551 ; CN6.38@9725,13050 9750,13050 10055,13355 10455,13355 10647.83,13547.83 v1(10671.83,13547.83)
SEG37: CN6.40 U11.98 U20.4 | length 3643.3
  TopLayer w5: v2(9360,12435) 9490,12565 9490,12790 9600,12900 9675,12900 CN6.40@9725,12950 ; v1(10692.85,13528.15) U11.98@10745.87,13528.15
  BottomLayer w5: v2(9360,12435) 9330,12405 9330,12280 9570,12040 9985,12040 10400,11625 10450,11625 10476,11599 U20.4@10476,11551 ; CN6.40@9725,12950 9775,13000 9775,13050 10070,13345 10470,13345 10653.15,13528.15 v1(10692.85,13528.15)
SEG38: R77.2 U20.33 | length 251.5
  TopLayer w5: R77.2@10475,12277.5 U20.33@10475,12529
SEG39: R78.2 U20.34 | length 251.5
  TopLayer w5: R78.2@10375,12277.5 U20.34@10375,12529
SEG40: JP7.1 U20.1 | length 3282
  TopLayer w5: v2(9400,13375) 9425,13400 9750,13400 9950,13600 JP7.1@10075,13600
  BottomLayer w5: v2(9400,13375) 9360,13335 9360,12510 9300,12450 9300,12165 9455,12010 9940,12010 10176,11774 U20.1@10176,11551 U20.1@10175,11550
SEG41: JP8.1 U20.2 | length 3201.6
  TopLayer w5: v2(9400,13350) 9440,13390 9765,13390 9850,13475 JP8.1@10075,13475
  BottomLayer w5: v2@9405,13355 9370,13320 9370,12495 9310,12435 9310,12270 9560,12020 9955,12020 10276,11699 U20.2@10276,11551
SEG42: CN6.21 U11.80 U20.35 | length 3696.9
  TopLayer w5: v2(10150,12350) 10276,12476 U20.35@10276,12530 ; v1(10692.48,13882.48) U11.80@10745.87,13882.48
  BottomLayer w5: CN6.21@9615,13850 9600,13850 9505,13755 9505,13298.43 9450,13243.43 9450,12390 9565,12275 10075,12275 v2(10150,12350) ; CN6.21@9625,13850 9650,13850 9700,13900 9900,13900 9917.52,13882.48 v1(10692.48,13882.48)
SEG43: CN6.24 U11.83 U20.36 | length 3418.6
  TopLayer w5: v2(10100.44,12375.44) 10176,12451 U20.36@10176,12530 ; v1(10669.57,13823.43) U11.83@10745.87,13823.43
  BottomLayer w5: v2(10100.44,12375.44) 10030,12305 9580,12305 9480,12405 9480,13231 9535,13286 9535,13635 9600,13700 9675,13700 CN6.24@9725,13750 9750,13750 9823.43,13823.43 v1(10669.57,13823.43)
SPEAKER+: CN3.2 U27.8 | length 5526.3
  TopLayer w20: U27.8@10661.61,10059.69 10661.61,10086.61 v2(10675,10100)
  BottomLayer w20: v2(10675,10100) 10705,10130 10705,10330 11025,10650 11350,10650 11500,10500 12350,10500 12800,10950 12800,12475 12775,12500 12775,13375 12725,13425 12725,13515.55 CN3.2@12841.93,13632.48
SPEAKER-: C74.2 CN3.1 R121.2 U25.2 U27.5 | length 5927.3
  TopLayer w12: U27.5@10738.39,10059.69 10785.31,10059.69 10845,10000 10940,10000 10967.5,10027.5 11018.85,10027.5 11045,10001.35 11045,9867.5 11025,9847.5 R121.2@11000,9847.5 ; C74.2@11000,10027.5 11000,10175 11075.39,10250.39 U25.2@11075.39,10550
  BottomLayer w20: U25.2@11075.39,10550 11225.39,10400 12350,10400 12900,10950 12900,12500 12855,12545 12855,13355 12975,13475 CN3.1@13100,13475
SPI1_MISO_3V3: CN14.7 U16.7 | length 2229.7
  TopLayer w5: U16.7@11039.16,12234.06 11039.16,12210.84 11055,12195 11155,12195 11225,12125 11225,11975 11330,11870 11680,11870 11810,11740 12035,11740 12120,11655 12120,11455 12455,11120 12455,11076.73 CN14.7@12519.02,11012.72
SPI1_MOSI_3V3: CN14.3 U15.7 | length 2207.6
  TopLayer w5: U15.7@11414.16,12234.06 11414.16,12185.84 11475,12125 11475,11975 11550,11900 11725,11900 11855,11770 12080,11770 12150,11700 12150,11500 12255,11395 12630,11395 12680,11345 12680,11200 12645,11165 12566.73,11165 CN14.3@12519.02,11212.72
SPI1_SCK_3V3: CN14.2 U14.7 | length 2040.5
  TopLayer w5: U14.7@11164.16,12234.06 11164.16,12210.84 11225,12150 11325,12150 11350,12125 11350,12000 11470,11880 11695,11880 11825,11750 12050,11750 12130,11670 12130,11470 12225,11375 12556.73,11375 CN14.2@12619.02,11312.72
SPI2_MISO_3V3: CN4.7 U16.6 | length 2313.6
  TopLayer w5: U16.6@11058.84,12234.06 11058.84,12266.16 11050,12275 11050,12350 11110,12410 12460,12410 12545,12495 12545,12970 12617.91,13042.91 CN4.7@12671.65,13042.91 12674.57,13040 CN4.7@12671.65,13040
SPI2_MOSI_3V3: CN4.3 U15.6 | length 1820
  TopLayer w5: U15.6@11433.84,12234.06 11433.84,12266.16 11425,12275 11425,12350 11455,12380 12475,12380 12575,12480 12575,12625 12725,12775 12725,12855 12710.31,12869.69 CN4.3@12671.65,12869.69
SPI2_SCK_3V3: CN4.5 U14.6 | length 2122
  TopLayer w5: U14.6@11183.84,12234.06 11183.84,12261.16 11175,12270 11175,12375 11200,12400 12465,12400 12555,12490 12555,12886.3 12623.7,12955 CN4.5@12680,12955
STM_JTCK_SWCLK: CN10.3 U23.37 | length 374.6
  TopLayer w5: U23.37@12022.32,10686.73 12161.73,10686.73 12225,10750 12300,10750 CN10.3@12350,10800
STM_JTMS_SWDIO: CN10.1 U23.34 | length 476.8
  TopLayer w5: U23.34@11923.9,10627.68 11923.9,10648.9 11935,10660 11975,10660 11985,10650 12300,10650 CN10.1@12350,10700
STM_RST: C56.2 R87.1 U23.7 | length 331.5
  TopLayer w5: C56.2@11744.5,11050 11744.5,11079.5 11752.5,11087.5 R87.1@11752.5,11125 11774,11125 11811,11088 11849,11088 11866,11071 11866,11033 11845.16,11012.16 U23.7@11845.16,10962.32
SWIM_PU_CTRL: U23.4 | length 282.4
  TopLayer w5: U23.4@11904.21,10962.32 11904.21,11004.21 12000,11100 12105,11100
T_JRST: D8.3 JP10.3 RS1.11 U23.19 | length 3169.7
  TopLayer w5: v2(11625,11670) 11625,11350 11595,11320 11595,10890 11610,10875 11610,10815 11639.84,10785.16 U23.19@11687.68,10785.16 ; v2(12050,12000) 12225,12000 12260,12035 12260,12135 12320.47,12195.47 RS1.11@12380,12195.47 ; 12195,12000 12200,11995 12205,12000 ; D8.3@12200,11925.5 12200,12000
  BottomLayer w5: v2(11625,11670) 11635,11680 11730,11680 12255,12205 12255,12587.57 11992.57,12850 JP10.3@11950,12850
T_SWDIO_IN: U19.2 U23.25 | length 1946.9
  TopLayer w5: v2(11550,11775) 11525,11750 11525,11200 11360,11035 11360,10840 11572.32,10627.68 U23.25@11746.73,10627.68 ; v2(11625,11925) 11625,12130 11640,12145 11660,12145 11665.16,12139.84 U19.2@11665.16,12115.94
  BottomLayer w5: v2(11550,11775) 11625,11850 v2(11625,11925)
T_SWO: U19.3 U23.16 U23.31 | length 1778.9
  TopLayer w5: v2(11675,11800) 11820,11655 11820,11495 11615,11290 11615,10960 11640,10935 11640,10860 11655.79,10844.21 11720.79,10844.21 11750,10815 v2(11750,10775) ; v2(11675,11925) 11675,12090 11684.84,12099.84 U19.3@11684.84,12115.94 ; v2(11850,10675) 11864.84,10660.16 U23.31@11864.84,10627.68
  BottomLayer w5: v2(11675,11800) v2(11675,11925) ; v2(11750,10775) v2(11850,10675)
U5V: C5.1 CN1.1 JP12.5 R86.1 U7.5 | length 10191.9
  TopLayer w12: v2(9900,11950) 10000,12050 R86.1@10147.5,12050 ; C5.1@12669.5,14800 12725,14800 CN1.1@12775,14750 ; U7.5@12681.3,14700 v1(12720,14700)
  BottomLayer w12: 8900,11950 v2(9900,11950) ; v1(12720,14700) 12725,14700 CN1.1@12775,14750
  BottomLayer w50: 9200,11480 9170,11450 8950,11450 8900,11500 8900,15000 9325,15425 12795,15425 12825,15395 12825,14858 12775,14808 CN1.1@12775,14750 ; 9200,11500 JP12.5@9200,11550
U5V_ST_LINK: CN11.1 JP12.7 R10.1 | length 8153.6
  TopLayer w5: R10.1@12594.5,10800 12725,10800 CN11.1@12800,10725
  BottomLayer w50: JP12.7@9300,11550 9300,11025 9450,10875 9450,10080 9150,9780 9150,9210 9440,8920 12440,8920 12700,9180 12700,10670 12755,10725 CN11.1@12800,10725
USART2_CTS: U2.6 U8.16 | length 509.4
  TopLayer w5: U2.6@10209.84,14584.06 10209.84,14540.16 10265,14485 10265,14335 10390.75,14209.25 U8.16@10390.75,14149.61
USART2_RTS: U4.7 U8.14 | length 1643.6
  TopLayer w5: U4.7@10315.16,14584.06 10315.16,14560.16 10305,14550 10280,14550 10260,14570 10260,14665 10225,14700 10075,14700 9930,14555 9930,14195 10030,14095 10280,14095 10416.34,13958.66 U8.14@10416.34,13850.39
USART2_RXD: JP5.3 U8.17 | length 611.5
  TopLayer w5: JP5.3@10275,13725 10300,13700 10350,13700 10450,13800 10450,14000 10365.16,14084.84 U8.17@10365.16,14149.61
USART2_TXD: U4.6 U8.13 U17.3 | length 4483.6
  TopLayer w5: U17.3@8975,12106.1 9031.1,12106.1 9085,12160 9160,12160 9200,12200 9200,12350 9405,12555 9405,13245 9360,13290 9360,13460 9600,13700 9750,13700 9830,13780 10355,13780 10390.75,13815.75 10390.75,13959.25 10265,14085 10015,14085 9920,14180 9920,14570 10060,14710 10305,14710 10325,14690 10325,14620 10334.84,14610.16 U4.6@10334.84,14584.06 ; U8.13@10390,13851.14 U8.13@10390.75,13850.39
USART3_RXD: U5.6 U5.7 U8.15 | length 633.4
  TopLayer w5: v2(10390,14450) 10390,14385 10490,14285 10490,14215 10475,14200 10435,14200 10416.34,14181.34 U8.15@10416.34,14149.61 ; U5.7@10440.16,14584.06 10440.16,14554.84 10445,14550 v2(10460,14550) 10459.84,14550.16 U5.6@10459.84,14584.06
  BottomLayer w5: v2(10390,14450) 10405,14465 10445,14465 10460,14480 v2(10460,14550)
USART3_TXD: U3.6 U3.7 U8.12 | length 2017.5
  TopLayer w5: U8.12@10365,13850.55 U8.12@10365.16,13850.39 10365.16,13880.16 10375,13890 10375,13950 10250,14075 10000,14075 9910,14165 9910,14585 10045,14720 10480,14720 10510,14690 10510,14565 10525,14550 10580,14550 10584.84,14554.84 U3.6@10584.84,14584.06 ; 10565.16,14550.16 U3.7@10565.16,14584.06
USB_DM: R104.1 U23.32 | length 523
  TopLayer w5: U23.32@11884.53,10627.68 11884.53,10540.47 12000,10425 R104.1@12272.5,10425
USB_DP: R97.1 U23.33 | length 479.5
  TopLayer w5: U23.33@11904.21,10627.68 11904.21,10545.79 11950,10500 12125,10500 12150,10525 R97.1@12272.5,10525
VDD: B2.1 B2.4 C7.1 C8.1 C9.2 C10.2 C12.2 C42.2 C43.2 C45.1 C46.2 C49.1 CN8.1 CN9.1 CN9.2 JP4.1 JP13.2 R12.2 R21.2 R26.1 R36.2 R44.2 R50.2 R51.2 R52.2 R53.2 R59.1 R64.1 R67.2 R68.2 R73.2 R76.2 R82.2 R90.1 R98.1 R99.2 R113.1 R114.2 R115.2 R116.2 R119.2 R133.1 R137.2 RV3.1 SW1.1 SW2.1 T3.4 TR1.2 TR2.2 TR4.2 U1.3 U1.5 U2.1 U3.1 U3.5 U4.1 U4.5 U5.1 U6.16 U9.5 U10.5 U12.5 U13.1 U13.5 U14.1 U14.5 U15.1 U15.5 U16.1 U19.8 | length 5470.6
  TopLayer w10: U12.5@11775.59,13531.69 11775.59,13479.41 11787.4,13467.6 T3.4@11787.4,13441.34
  TopLayer w12: R99.2@9800,10219.5 9800,10250 9847.5,10297.5 R98.1@9847.5,10350 ; U1.5@10149.02,14838.39 v1@10149.02,14864.02 ; v1(10170,14430) 10180.5,14419.5 C8.1@10180.5,14375 ; v1@10170.47,14430.47 U2.1@10170.47,14465.94 ; U4.1@10295.47,14465.94 v1(10295.47,14429.53) 10305.5,14419.5 C9.2@10305.5,14375 ; U4.5@10354.53,14584.06 10354.53,14570.47 v1(10375,14550) ; v1(10360,14825) 10372.2,14812.8 U1.3@10400.98,14812.8 ; U5.1@10420.47,14465.94 v1(10420.47,14424.53) 10430.5,14414.5 C10.2@10430.5,14375 ; v1(10545,14425) 10555.5,14414.5 C12.2@10555.5,14375 ; v1@10545.47,14425.47 U3.1@10545.47,14465.94 ; v1(10552.5,13012.5) R44.2@10552.5,13050 ; U3.5@10604.53,14584.06 10634.06,14584.06 10652.5,14602.5 R12.2@10700,14602.5 ; v2(10650,14450) 10677.5,14422.5 R21.2@10700,14422.5 ; v1(10732.5,9277.5) R137.2@10775,9277.5 ; v1(10735,11760) TR1.2@10787.5,11760 ; R67.2@10750,11930.5 R73.2@10850,11930.5 ; R73.2@10850.5,11930 v1(10900,11930) ; v1@10900.5,11930.5 R68.2@10950,11930.5 ; v1(10945,11760) TR2.2@10987.5,11760 ; U16.1@11019.47,12115.94 11020,12115.42 11020,12080 11030.5,12069.5 C45.1@11030.5,12025 ; U14.1@11145,12115.42 11145,12080 11155.5,12069.5 C46.2@11155.5,12025 ; U14.5@11203.53,12234.06 11215.94,12234.06 v1(11225,12225) ; v1@11269.47,12080.53 v1@11270,12080 ; U13.1@11270,12115.42 v1@11270,12080 ; C42.2@11280.5,12025 11280.5,12069.5 v1@11270,12080 ; U13.5@11328.53,12234.06 11340.94,12234.06 v2(11350,12225) ; v1(11387.5,10922.5) TR4.2@11387.5,10960 ; U15.1@11395,12115.42 11395,12080 11405.5,12069.5 C43.2@11405.5,12025 ; U15.5@11453.53,12234.06 11490.94,12234.06 v2(11500,12225) ; v2(11550,12100) 11555.5,12094.5 R64.1@11575,12094.5 ; R113.1@11575,10019.5 v1(11575,10050) ; R59.1@11575,12269.5 v1(11575,12300) ; U19.8@11645.47,12234.06 11645.47,12265.47 v2(11655.5,12275.5) C49.1@11655.5,12325 ; C7.1@11650,14469.5 v2(11650,14500) ; R26.1@11650,14530.5 v1@11709.5,14530.5 ; v1@11710.43,14531.43 U6.16@11710.43,14575.98 ; R114.2@11725,10019.5 v1(11725,10050) ; U12.5@11775.59,13531.69 v1(11775.59,13569.41) ; R115.2@11875,10019.5 v1(11875,10050) ; v5(11924,13479) R36.2@11924,13529.5 ; U10.5@11962.4,14146.85 11962.4,14167.4 11970,14175 v2(12050,14175) ; R116.2@12025,10019.5 v1(12025,10050) ; R119.2@12175,10019.5 v1(12175,10050) ; R133.1@12250,10027.5 v1(12292.5,10027.5) ; B2.1@12272.83,9087.5 B2.4@12627.17,9087.5 ; R76.2@12427.5,12100 v2(12465,12100) ; CN8.1@12650,12250 v1(12650,12300) ; v2(12650,14125) R53.2@12697.5,14125 ; v2(12700,12500) R50.2@12700,12452.5 R52.2@12850,12452.5 ; v2(12725,11025) R90.1@12780.5,11025 ; v2(12725,11525) R82.2@12780.5,11525
  TopLayer w15: JP4.1@11750,14050 11750,14092 11775.59,14117.59 U9.5@11775.59,14156.69
  TopLayer w30: SW1.1@9625,12225 9625,11720 9725,11620 JP13.2@9725,11525
  MidLayer1 w5: 11144.47,12080.53 11145,12080
  MidLayer1 w12: v1(10375,14550) 10390,14535 10390,14513 ; JP4.1@11750,14050 11800,14000 11800,13825
  BottomLayer w12: v1(9825,10275) 9825,9300 v2(9875,9250)
  other v1: 12425,9087.5 11155.5,12050 11274.71,12075.29 11400,12075 11710,14530 10150,14865
  other v2: 11025,12075 10650,14600
VDD_ADJ: C52.1 JP13.1 R94.2 TP7.1 U24.2 | length 2767.4
  TopLayer w12: TP7.1@9275,10450 9525,10700 9825,10700 9852.5,10672.5 9915,10672.5
  TopLayer w15: R94.2@9900,10672.5 9942.5,10672.5 9990,10625 U24.2@10076.18,10625
  TopLayer w20: 10140,10625 10140,10630 10175,10665 10215,10625
  TopLayer w30: JP13.1@9625,11525 9625,11485 9695,11415 9695,11055 9850,10900 10070,10900 10175,10795 10175,10625 ; U24.2@10076.18,10625 U24.2@10525,10625
VDD_MCU: C17.1 C21.1 C23.1 C24.1 C26.1 JP4.2 L1.1 U11.11 U11.28 U11.50 U11.75 U11.100 | length 1394.1
  TopLayer w12: C23.1@10550,13480.5 10641.5,13480.5 10649.78,13488.78 U11.100@10745.87,13488.78 ; C17.1@10805.5,14225 v2(10805.5,14088.28) 10813.78,14080 U11.75@10813.78,14029.13 ; U11.11@11010.63,13420.87 11010.63,13312.37 11044.5,13278.5 C26.1@11044.5,13225 ; U11.28@11354.13,13528.15 11496.85,13528.15 11505.5,13519.5 C24.1@11550,13519.5 ; U11.50@11354.13,13961.22 11407.22,13961.22 v1(11408,13962) 11465,13962 11472.5,13969.5 C21.1@11550,13969.5 ; L1.1@11452,13125.5 v2(11452,13440)
  MidLayer1 w12: v2(11010.63,13345) 11010.63,13417.37
  other v2: 11452,13415 10695,13488.78 11405,13528.15
VDDA: C32.1 C34.1 L1.2 R41.2 U11.22 | length 771.7
  TopLayer w12: U11.22@11227.17,13420.87 11227.17,13262.83 11365,13125 L1.2@11397.5,13125 11397.5,13105 11410,13092.5 11547.5,13092.5 ; C32.1@11500,12994.5 11500,13020 11510,13030 C34.1@11575,13030 11575,13065 11547.5,13092.5 ; R41.2@11547.5,13125 11547.5,13092.5
VLCD: C22.1 CN6.31 U11.6 | length 1866.6
  TopLayer w12: C22.1@10847.5,13225 10847.5,13242.5 10912,13307 10912,13420.66 U11.6@10912.2,13420.87
  BottomLayer w12: CN6.31@9625,13350 9675,13400 9750,13400 10000,13650 10400,13650 10455,13705 10695,13705 10912,13488 v1(10912,13368)
VREF+: C27.1 R41.1 TP1.1 U11.21 | length 1129.8
  TopLayer w10: v1(11600,13155) 11602.5,13152.5 R41.1@11602.5,13125
  TopLayer w12: C27.1@11194.5,13225 11194.5,13247.33 11207.48,13260.31 U11.21@11207.48,13420.87 ; TP1.1@11575,13600 11600,13575 v1(11600,13155)
  MidLayer1 w12: v2(11197.17,13250) 11222.17,13225 11300,13225 11350,13175 11580,13175 v1(11600,13155)
VREF-: R40.2 U11.20 | length 353.2
  TopLayer w12: U11.20@11187.8,13420.87 11187.8,13307.8 11175,13295 11175,13160 11210,13125 R40.2@11247.5,13125
pads on no net: CN2.1 CN2.4 CN2.9 CN3.G1 CN3.G2 CN4.0 CN4.1 CN4.8 CN5.9 CN8.0 CN8.7 CN10.5 CN14.0 CN14.4 CN14.5 CN14.6 D3.1 D4.1 D5.1 D6.1 D7.1 D8.1 MP1.0 MP2.0 RS1.1 RS1.2 RS1.15 RS1.16 U6.1 U6.4 U6.5 U6.6 U6.7 U6.13 U6.14 U6.15 U8.4 U8.18 U8.19 U8.21 U11.0 U17.2 U23.11 U23.12 U23.13 U23.14 U23.21 U23.22 U23.28 U23.38 U23.39 U23.40 U23.41 U23.42 U23.43 U23.45 U23.46 U30.0 X1.2 X1.3
copper on no net: | length 4000
  MidLayer1 w5: 12025,15250 12775,15250 ; 12150,15125 12150,15375 ; 12275,15125 12275,15375 ; 12400,15125 12400,15375 ; 12525,15125 12525,15375 ; 12650,15125 12650,15375 ; 12025,15125 12025,15375 12775,15375 12775,15125 12025,15125

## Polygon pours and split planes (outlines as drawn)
+3V3 on TopLayer (hatched 90Degree grid 10 track 10, remove dead copper): 9775,11710 9775,11455 9825,11405 10070,11405 10165,11310 10165,11165 10200,11130 10210,11120 10210,10920 10265,10865 10735,10865 10770,10900 10770,11315 10735,11350 10225,11350 10030,11545 9920,11545 9885,11580 9885,11685 10095,11895 10410,11895 10425,11910 10425,11940 10410,11955 10010,11955 9775,11720
PC8 on TopLayer (hatched 90Degree grid 12 track 15, remove dead copper): 10115,15560 10115,14990 10230,14875 10570,14875 10730,14715 10730,14250 10840,14140 11250,14140 11340,14230 11340,14790 11415,14865 11930,14865 11975,14910 11975,15570 10115,15570
GND on TopLayer (hatched 90Degree grid 15 track 10, remove dead copper): 8775,15600 8775,8775 13275,8775 13275,15575 8775,15575
VDD_MCU on MidLayer1 (hatched 90Degree grid 10 track 10, remove dead copper): 10595,13323 11825,13323 11825,13983 11900,13983 11900,14310 11355,14310 11355,14175 10595,14175
VDD on MidLayer1 (hatched 90Degree grid 10 track 10, remove dead copper): 8775,8775 13275,8775 13275,15575 11985,15575 11985,14925 11930,14870 11725,14870 11377.16,14522.16 11377.16,14275 11925,14275 11925,13995 11700,13995 11700,13350 10600,13350 10600,14175 10725,14175 10725,14787 10617,14895 10060,14895 10060,14775 10592,14775 10592,14533 10042,14533 10042,14280 10275,14280 10275,14165 9710,14165 9710,12510.2 9402,12510.2 9402,11645 9684,11363 10540,11363 10540,10323 10892,10323 11355,9860 12600,9860 12140,9400 8775,9400
+3V3 on MidLayer1 (hatched 90Degree grid 10 track 10, remove dead copper): 10350,11875 10475,11875 10475,12050 10625,12200 11525,12200 11600,12125 11600,12050 11700,12050 11700,12200 11575,12325 10575,12325 10350,12100
+3V3 on MidLayer1 (hatched 90Degree grid 10 track 10, remove dead copper): 9725,14150 10275,14150 10275,14275 10075,14275 10075,14525 10600,14525 10600,14775 10075,14775 10075,14905 10125,14905 10125,15575 8775,15575 8775,9300 10925,9300 11000,9375 12525,9375 12800,9650 12800,10300 12675,10425 12450,10425 12325,10550 12325,11275 11450,11275 11450,10350 11475,10325 11550,10250 12600,10250 12600,10112.72 12519.02,10112.72 12350,9943.7 11315,9943.7 10908.7,10350 9860,10350 9860,11060 10340,11060 10340,11240 9700,11240 9400,11540 8960,11540 8960,11775 9400,11775 9400,12455 9445,12500 9750,12500 9750,14150
+5V on MidLayer1 (hatched 90Degree grid 10 track 10, remove dead copper): 8950,11775 9425,11775 9625,11575 9625,11500 9725,11400 10550,11400 10550,10350 9875,10350 9875,11050 10350,11050 10350,11250 9700,11250 9400,11550 8950,11550
PC8 on MidLayer1 (hatched 90Degree grid 12 track 15, remove dead copper): 10125,15565 10125,14925 10170,14880 10575,14880 10730,14725 10730,14250 10883.2,14096.8 11280,14096.8 11355,14171.8 11355,14515 11695,14855 11720,14880 11930,14880 11975,14925 11975,15565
